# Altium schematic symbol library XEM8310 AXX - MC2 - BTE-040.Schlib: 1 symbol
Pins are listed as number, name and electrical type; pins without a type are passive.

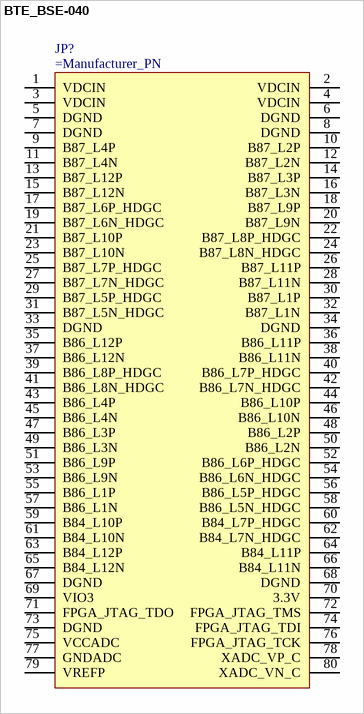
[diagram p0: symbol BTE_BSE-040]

## BTE_BSE-040
designator JP?
pins: 1 VDCIN, 2 VDCIN, 3 VDCIN, 4 VDCIN, 5 DGND, 6 DGND, 7 DGND, 8 DGND, 9 B87_L4P, 10 B87_L2P, 11 B87_L4N, 12 B87_L2N, 13 B87_L12P, 14 B87_L3P, 15 B87_L12N, 16 B87_L3N, 17 B87_L6P_HDGC, 18 B87_L9P, 19 B87_L6N_HDGC, 20 B87_L9N, 21 B87_L10P, 22 B87_L8P_HDGC, 23 B87_L10N, 24 B87_L8N_HDGC, 25 B87_L7P_HDGC, 26 B87_L11P, 27 B87_L7N_HDGC, 28 B87_L11N, 29 B87_L5P_HDGC, 30 B87_L1P, 31 B87_L5N_HDGC, 32 B87_L1N, 33 DGND, 34 DGND, 35 B86_L12P, 36 B86_L11P, 37 B86_L12N, 38 B86_L11N, 39 B86_L8P_HDGC, 40 B86_L7P_HDGC, 41 B86_L8N_HDGC, 42 B86_L7N_HDGC, 43 B86_L4P, 44 B86_L10P, 45 B86_L4N, 46 B86_L10N, 47 B86_L3P, 48 B86_L2P, 49 B86_L3N, 50 B86_L2N, 51 B86_L9P, 52 B86_L6P_HDGC, 53 B86_L9N, 54 B86_L6N_HDGC, 55 B86_L1P, 56 B86_L5P_HDGC, 57 B86_L1N, 58 B86_L5N_HDGC, 59 B84_L10P, 60 B84_L7P_HDGC, 61 B84_L10N, 62 B84_L7N_HDGC, 63 B84_L12P, 64 B84_L11P, 65 B84_L12N, 66 B84_L11N, 67 DGND, 68 DGND, 69 VIO3, 70 3.3V, 71 FPGA_JTAG_TDO, 72 FPGA_JTAG_TMS, 73 DGND, 74 FPGA_JTAG_TDI, 75 VCCADC, 76 FPGA_JTAG_TCK, 77 GNDADC, 78 XADC_VP_C, 79 VREFP, 80 XADC_VN_C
